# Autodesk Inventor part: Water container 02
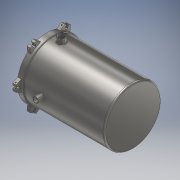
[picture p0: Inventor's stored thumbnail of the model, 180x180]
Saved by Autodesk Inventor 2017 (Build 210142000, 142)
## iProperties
Created: 2020-03
Part Number: Water container 02
Material: Stainless Steel
Document SubType Name: Modeling
Designer: user
Density: 8 g/cm^3
Appearance: Semi-Polished
Author: user
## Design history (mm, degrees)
sketch "Sketch1"
  geometry: L1 (5, 0)-(300, 0); L2 (300, 0)-(300, -2); L3 (2, -100)-(0, -100); L4 (0, -100)-(0, -5); L5 (300, -2)-(5, -2); L6 (2, -5)-(2, -100); A1 r 5 centre (5, -5) between (5, 0) and (0, -5); A2 r 3 centre (5, -5) between (5, -2) and (2, -5); 1 further point
  constraints: 12 end point, 4 point on circle, 3 perpendicular, 2 centre point, 2 point on line, 2 tangent, 1 horizontal
  dimensions: "d0" = 300 distance of point (0, 0) L1.end; "d2" = 5 radius of A1; "d3" = 2 distance between parallel lines of L1 L5; "d4" = 100 distance between parallel lines of L3 L1; "d5" = 2 distance between parallel lines of L4 L6; "d6" = 3 radius of A2
revolve "Revolution1" sketch "Sketch1" stored, may be unused: angle "d7" = 90 deg
sketch "Sketch2"
  geometry: L1 (-300, 100)-(-300, -100) reference; C1 r 12.7 at (-250, 0); 1 further point
  constraints: 1 centre point
  dimensions: "d8" = 25.4 diameter of C1; "d9" = 50 distance from line of C1.centre L1
extrude "Extrusion1" join sketch "Sketch2" stored distance "d10" = 10; taper "d11" = 0 deg
sketch "Sketch3"
  geometry: C1 r 12.7 at (-250, 0); A1 r 12.7 centre (-250, 0) between (-262.7, 0) and (-237.3, 0) reference; 1 further point
  constraints: 1 centre point, 1 coincident
extrude "Extrusion2" join sketch "Sketch3" distance "d12" = 20; taper "d13" = 0 deg
sketch "Sketch4"
  geometry: L1 (262.7, 20)-(262.7, 0) reference; L2 (262.7, 20)-(237.3, 20) reference; L3 (262.7, 16)-(262.7, 18); L4 (250, 20)-(250, 24.983); A1 r 1 centre (262.7, 17) between (262.7, 16) and (262.7, 18); 1 further point
  constraints: 4 end point, 3 point on line, 2 point on circle, 1 centre point, 1 collinear, 1 midpoint, 1 vertical
  dimensions: "d14" = 2 diameter of A1; "d15" = 3 distance from line of L2 A1.centre
revolve "Revolution2" sketch "Sketch4" stored, may be unused: angle "d16" = 90 deg
sketch "Sketch5"
  geometry: C1 r 11.5 at (0, 0); 1 further point
  constraints: 1 centre point
  dimensions: "d17" = 23 diameter of C1
extrude "Extrusion3" cut sketch "Sketch5" distance "d18" = 25; taper "d19" = 0 deg
fillet "Fillet1" dims "d20" = 2
sketch "Sketch6"
  geometry: C1 r 104 at (0, 0); C2 r 100 at (0, 0); 1 further point
  constraints: 2 centre point, 1 coincident
  dimensions: "d21" = 208 diameter of C1
extrude "Extrusion4" join sketch "Sketch6" distance "d22" = 20; taper "d23" = 0 deg
sketch "Sketch7"
  geometry: L1 (-20, 102.059)-(-11.634, 120); L2 (-11.634, 120)-(11.634, 120); L3 (11.634, 120)-(20, 102.059); L4 (0, 0)-(0, -125.334); A1 r 104 centre (0, 0) between (-20, 102.059) and (20, 102.059) reference; A2 r 104 centre (0, 0) between (20, 102.059) and (-20, 102.059); 1 further point
  constraints: 8 end point, 4 point on circle, 1 centre point, 1 coincident, 1 concentric, 1 horizontal, 1 vertical, 1 other
  dimensions: "d24" = 120 distance from line of L4.start L2; "d25" = 40 distance of L3.end L1.start; "d26" = 50 deg angle of L3 L1
extrude "Extrusion5" join sketch "Sketch7" distance "d27" = 12; taper "d28" = 0 deg
sketch "Sketch8"
  geometry: L1 (-11.634, 120)-(11.634, 120) reference; L2 (0, 120)-(0, 102); L3 (-4.5, 111)-(-4.5, 120); L4 (4.5, 111)-(4.5, 120); L5 (-4.5, 120)-(4.5, 120); A1 r 4.5 centre (0, 111) between (-4.5, 111) and (4.5, 111); 1 further point
  constraints: 8 end point, 2 midpoint, 2 point on circle, 2 point on line, 2 tangent, 2 vertical, 1 centre point, 1 collinear, 1 perpendicular
  dimensions: "d29" = 9 diameter of A1; "d44" = 9 distance from line of L1 A1.centre
extrude "Extrusion6" cut sketch "Sketch8" distance "d30" = 12; taper "d31" = 0 deg
workplane "Work Plane1"
sketch "Sketch9"
  geometry: L1 (-300, 120)-(-288, 120) reference; C1 r 2 at (-294, 115.5); 1 further point
  constraints: 1 centre point
  dimensions: "d33" = 4 diameter of C1; "d34" = 4.5 distance from line of L1 C1.centre
extrude "Extrusion7" cut sketch "Sketch9" stored distance "d35" = 12; taper "d36" = 0 deg
pattern_circular "Circular Pattern1" dims angle "d38" = 360 deg
sketch "Sketch10"
  geometry: L1 (300, 6.173)-(300, -1.621) reference; L2 (300, -1)-(298, -1); L3 (298, -1)-(298, 3); L4 (298, 3)-(300, 3); L5 (300, 3)-(300, -1); L6 (300, -198)-(300, -2) reference; L7 (300, -100)-(312.237, -100); 1 further point
  constraints: 10 end point, 2 horizontal, 2 parallel, 1 midpoint, 1 perpendicular, 1 point on line
  dimensions: "d40" = 2 distance of L3.end L4.end; "d41" = 4 distance of L2.end L3.end; "d42" = 99 distance between parallel lines of L2 L7
revolve "Revolution3" sketch "Sketch10" stored, may be unused: angle "d43" = 90 deg
workplane "Work Plane2"
sketch "Sketch17"
  geometry: C1 r 8.5 at (220, -100); 1 further point
  constraints: 1 centre point
  dimensions: "d82" = 100 vertical distance of point (0, 0) C1.centre; "d83" = 220 horizontal distance of point (0, 0) C1.centre; "d85" = 17 diameter of C1
extrude "Extrusion10" cut sketch "Sketch17" distance "d86" = 250; taper "d87" = 0 deg
workplane "Work Plane5"
sketch "Sketch18"
  geometry: C1 r 10 at (220, -100); C2 r 8.5 at (220, -100); 2 further points
  constraints: 2 centre point, 1 coincident
  dimensions: "d90" = 20 diameter of C1; "d91" = 17 diameter of C2; "d92" = 100 vertical distance of point (0, 0) C1.centre; "d93" = 220 horizontal distance of point (0, 0) C1.centre
extrude "Extrusion11" join sketch "Sketch18" stored distance "d94" = 250; taper "d95" = 0 deg
workplane "Work Plane6"
sketch "Sketch20"
  geometry: C1 r 10 at (120, -100); 1 further point
  constraints: 1 centre point
  dimensions: "d100" = 20 diameter of C1; "d101" = 100 vertical distance of point (0, 0) C1.centre; "d102" = 120 horizontal distance of point (0, 0) C1.centre
extrude "Extrusion12" join sketch "Sketch20" stored distance "d103" = 10; taper "d104" = 0 deg
sketch "Sketch21"
  geometry: A1 r 10 centre (-120, 100) between (-110, 100) and (-130, 100) reference; A2 r 10 centre (-120, 100) between (-130, 100) and (-110, 100) reference; A3 r 8.5 centre (-120, 100) between (-111.5, 100) and (-128.5, 100); A4 r 8.5 centre (-120, 100) between (-128.5, 100) and (-111.5, 100); 1 further point
  constraints: 4 point on circle, 2 centre point, 1 other
  dimensions: "d105" = 1.5 radial gap between concentric circles of A1 A3
extrude "Extrusion13" cut sketch "Sketch21" distance "d106" = 10; taper "d107" = 0 deg
body "Solid1"
node "Projected Loop1"
